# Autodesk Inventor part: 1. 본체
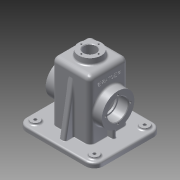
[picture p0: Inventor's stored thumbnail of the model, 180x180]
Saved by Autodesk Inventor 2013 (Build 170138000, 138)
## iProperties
Created: 2016-01
Part Number: 1. 본체
Material: 알루미늄 6061
Document SubType Name: Modeling
Designer: Administrator
Density: 2.71 g/cm^3
Mass: 875.229 g
Surface Area: 901.683 cm^2
Volume: 322.963 cm^3
Author: Administrator
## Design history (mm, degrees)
sketch "스케치1"
  geometry: L1 (65, -57.5)-(-65, -57.5); L2 (-65, -57.5)-(-65, 57.5); L3 (-65, 57.5)-(65, 57.5); L4 (65, 57.5)-(65, -57.5); L5 (65, -57.5)-(-65, 57.5); L6 (-65, -57.5)-(65, 57.5); 1 further point
  constraints: 12 end point, 2 midpoint, 2 parallel, 1 horizontal, 1 perpendicular
  dimensions: "d0" = 130 distance of L2.end L3.end; "d2" = 115 distance of L3.end L1.start
extrude "돌출1" new body sketch "스케치1" distance "d3" = 8; taper "d4" = 0 deg
fillet "모깎기1" dims "d5" = 15
sketch "스케치2"
  geometry: C1 r 7.5 at (-50, -42.5); C2 r 7.5 at (-50, 42.5); C3 r 7.5 at (50, -42.5); C4 r 7.5 at (50, 42.5); A1 r 15 centre (-50, -42.5) between (-65, -42.5) and (-50, -57.5) reference; A2 r 15 centre (50, -42.5) between (50, -57.5) and (65, -42.5) reference; A3 r 15 centre (50, 42.5) between (65, 42.5) and (50, 57.5) reference; A4 r 15 centre (-50, 42.5) between (-50, 57.5) and (-65, 42.5) reference; 1 further point
  constraints: 4 centre point, 4 coincident
  dimensions: "d6" = 15 diameter of C1; "d7" = 15 diameter of C2; "d8" = 15 diameter of C3; "d9" = 15 diameter of C4
extrude "돌출2" join sketch "스케치2" distance "d10" = 3; taper "d11" = 0 deg
sketch "스케치3"
  geometry: L1 (50, 52.5)-(-50, 52.5); L2 (-60, 42.5)-(-60, -42.5); L3 (-50, -52.5)-(50, -52.5); L4 (60, -42.5)-(60, 42.5); L5 (60, 52.5)-(-60, -52.5); L6 (-60, 52.5)-(60, -52.5); A1 r 10 centre (-50, -42.5) between (-60, -42.5) and (-50, -52.5); A2 r 10 centre (50, -42.5) between (50, -52.5) and (60, -42.5); A3 r 10 centre (50, 42.5) between (60, 42.5) and (50, 52.5); A4 r 10 centre (-50, 42.5) between (-50, 52.5) and (-60, 42.5); 1 further point
  constraints: 12 end point, 8 point on circle, 8 point on line, 8 tangent, 4 centre point, 3 equal radius, 2 midpoint, 2 parallel, 1 horizontal, 1 perpendicular
  dimensions: "d12" = 120 distance of L5.start L6.start; "d14" = 105 distance of L6.start L5.end; "d15" = 10 radius of A1
extrude "돌출3" join sketch "스케치3" distance "d16" = 2; taper "d17" = 0 deg
sketch "스케치4"
  geometry: C1 r 7.5 at (0, 0) reference; C2 r 7.5 at (100, -85) reference; C3 r 7.5 at (0, -85) reference; C4 r 7.5 at (0, 0) reference; C5 r 7.5 at (100, 0) reference; C6 r 7.5 at (100, -85) reference; C7 r 7.5 at (0, -85) reference; C8 r 7.5 at (0, 0) reference; C9 r 7.5 at (100, 0) reference; 1 further point
hole "구멍1" sketch "스케치4" at (0, 0), (0, -85), (100, 0), (100, -85) diameter "d18" = 5; stored, may be unused: countersink angle "d22" = 90 deg, drill point angle "d24" = 118 deg; dims "d19" = 6, "d20" = 4, "d21" = 2, "d23" = 8
sketch "스케치5"
  geometry: L1 (-32.5, -32.5)-(32.5, -32.5); L2 (32.5, -32.5)-(32.5, 32.5); L3 (32.5, 32.5)-(-32.5, 32.5); L4 (-32.5, 32.5)-(-32.5, -32.5); L5 (-32.5, -32.5)-(32.5, 32.5); L6 (32.5, -32.5)-(-32.5, 32.5); 1 further point
  constraints: 12 end point, 2 midpoint, 2 parallel, 1 horizontal, 1 perpendicular
  dimensions: "d25" = 65 distance of L2.end L3.end; "d27" = 65 distance of L1.end L2.end
extrude "돌출4" join sketch "스케치5" distance "d28" = 100; taper "d29" = 0 deg
fillet "모깎기2" dims "d30" = 8
fillet "모깎기3" dims "d31" = 8
sketch "스케치6"
  geometry: C1 r 20 at (0, 0); 1 further point
  constraints: 1 centre point, 1 coincident
  dimensions: "d32" = 40 diameter of C1
extrude "돌출5" join sketch "스케치6" distance "d33" = 10; taper "d34" = -5 deg
sketch "스케치7"
  geometry: L1 (27.5, 27.5)-(-27.5, 27.5); L2 (-27.5, 27.5)-(-27.5, -27.5); L3 (-27.5, -27.5)-(27.5, -27.5); L4 (27.5, -27.5)-(27.5, 27.5); L5 (27.5, 27.5)-(-27.5, -27.5); L6 (-27.5, 27.5)-(27.5, -27.5); 1 further point
  constraints: 12 end point, 2 midpoint, 2 parallel, 1 horizontal, 1 perpendicular
  dimensions: "d35" = 55 distance of L2.end L3.end; "d37" = 55 distance of L3.end L1.start
extrude "돌출6" cut sketch "스케치7" distance "d38" = 105; taper "d39" = 0 deg
fillet "모깎기4" dims "d40" = 3
fillet "모깎기5" dims "d41" = 3
sketch "스케치8"
  geometry: C1 r 19.125 at (0, 0) reference
hole "구멍2" sketch "스케치8" at (0, 0) diameter "d42" = 21; stored, may be unused: countersink angle "d46" = 90 deg, drill point angle "d48" = 118 deg; dims "d43" = 6, "d44" = 4, "d45" = 2, "d47" = 8
node "작업 평면2"
sketch "스케치9"
  geometry: L1 (8, -33)-(0, -33) reference; L2 (0, -33)-(0, -25.071) reference; L3 (0, -25.071)-(-3, -25.071) reference; L4 (-3, -25.071)-(-3, -18) reference; L5 (-3, -18)-(10, -18) reference; L6 (10, 67)-(10, -18) reference; L7 (-3, 67)-(10, 67) reference; L8 (-3, 67)-(-3, 74.071) reference; L9 (-3, 74.071)-(0, 74.071) reference; L10 (0, 74.071)-(0, 82) reference; L11 (0, 82)-(8, 82) reference; L12 (8, 82)-(8, 77) reference; L13 (8, 77)-(10, 77) reference; L14 (10, 77)-(10, 67) reference; L15 (8, -28)-(8, -33) reference; L16 (10, -28)-(8, -28) reference; L17 (10, -18)-(10, -28) reference; L18 (-3, -18)-(-3, -10.929) reference; L19 (-3, -10.929)-(0, -10.929) reference; L20 (0, -10.929)-(0, 59.929) reference; L21 (0, 59.929)-(-3, 59.929) reference; L22 (-3, 59.929)-(-3, 67) reference; C1 r 27.5 at (-45, 24.5); 1 further point
  constraints: 1 centre point, 1 horizontal alignment
  dimensions: "d50" = 55 diameter of C1; "d51" = 55 distance from line of L6 C1.centre
extrude "돌출7" join sketch "스케치9" stored distance "d52" = 0; taper "d53" = 0 deg
sketch "스케치10"
  geometry: C1 r 27.5 at (0, 0) reference; 1 further point
hole "구멍3" sketch "스케치10" at (0, 0) diameter "d54" = 30; stored, may be unused: countersink angle "d58" = 90 deg, drill point angle "d60" = 118 deg; dims "d55" = 6, "d56" = 35, "d57" = 17, "d59" = 8
sketch "스케치16"
  geometry: C1 r 15 at (0, 0) reference; 1 further point
hole "구멍6" sketch "스케치16" at (0, 0) diameter "d113" = 30; stored, may be unused: countersink angle "d117" = 90 deg, drill point angle "d119" = 118 deg; dims "d114" = 6, "d115" = 35, "d116" = 17, "d118" = 8
sketch "스케치12"
  geometry: C1 r 10.5 at (0, 0) reference; 1 further point
  constraints: 1 horizontal alignment
  dimensions: "d72" = 14.5 distance of C1.centre point (-14.5, 0)
hole "구멍5" sketch "스케치12" at (-14.5, 0) diameter "d73" = 2.459; stored, may be unused: countersink angle "d77" = 90 deg, drill point angle "d79" = 118 deg; dims "d74" = 7, "d75" = 4, "d76" = 2, "d78" = 9
sketch "스케치13"
  geometry: L1 (19.125, 118)-(20, 108) reference; L2 (20, 108)-(24.5, 108) reference; L3 (32.5, 100)-(32.5, 80.5) reference; L4 (32.5, 80.5)-(47.5, 80.5) reference; L5 (47.5, 80.5)-(47.5, 70.5) reference; L6 (30.5, 68)-(27.5, 68) reference; L7 (27.5, 68)-(27.5, 100) reference; L8 (24.5, 103)-(10.5, 103) reference; L9 (10.5, 103)-(10.5, 118) reference; L10 (10.5, 118)-(13.271, 118) reference; L11 (13.271, 118)-(13.271, 109) reference; L12 (13.271, 109)-(14.5, 108.261) reference; L13 (14.5, 108.261)-(15.73, 109) reference; L14 (15.73, 109)-(15.73, 118) reference; L15 (15.73, 118)-(19.125, 118) reference; L16 (-20, 108)-(-19.125, 118) reference; L17 (-19.125, 118)-(-15.73, 118) reference; L18 (-15.73, 118)-(-15.73, 109) reference; L19 (-15.73, 109)-(-14.5, 108.261) reference; L20 (-14.5, 108.261)-(-13.271, 109) reference; L21 (-13.271, 109)-(-13.271, 118) reference; L22 (-13.271, 118)-(-10.5, 118) reference; L23 (-10.5, 118)-(-10.5, 103) reference; L24 (-10.5, 103)-(-24.5, 103) reference; L25 (-27.5, 100)-(-27.5, 68) reference; L26 (-27.5, 68)-(-30.5, 68) reference; L27 (-47.5, 70.5)-(-47.5, 80.5) reference; L28 (-47.5, 80.5)-(-32.5, 80.5) reference; L29 (-32.5, 80.5)-(-32.5, 100) reference; L30 (-24.5, 108)-(-20, 108) reference; L31 (-60, -2)-(-60, 0) reference; L32 (-60, 0)-(-65, 0) reference; L33 (-65, 0)-(-65, 8) reference; L34 (-65, 8)-(-32.5, 8) reference; L35 (-32.5, 8)-(-32.5, 25.5) reference; L36 (-32.5, 25.5)-(-47.5, 25.5) reference; L37 (-47.5, 25.5)-(-47.5, 35.5) reference; L38 (-30.5, 38)-(-27.5, 38) reference; L39 (-27.5, 38)-(-27.5, -2) reference; L40 (-27.5, -2)-(-60, -2) reference; L41 (60, 0)-(60, -2) reference; L42 (60, -2)-(27.5, -2) reference; L43 (27.5, -2)-(27.5, 38) reference; L44 (27.5, 38)-(30.5, 38) reference; L45 (47.5, 35.5)-(47.5, 25.5) reference; L46 (47.5, 25.5)-(32.5, 25.5) reference; L47 (32.5, 25.5)-(32.5, 8) reference; L48 (32.5, 8)-(65, 8) reference; L49 (65, 8)-(65, 0) reference; L50 (65, 0)-(60, 0) reference; L51 (-42.5, 25.5)-(-42.5, 8); L52 (47.5, 70.5)-(30.5, 70.5) reference; L53 (30.5, 70.5)-(30.5, 68) reference; L54 (-30.5, 68)-(-30.5, 70.5) reference; L55 (-30.5, 70.5)-(-47.5, 70.5) reference; L56 (-47.5, 35.5)-(-30.5, 35.5) reference; L57 (-30.5, 35.5)-(-30.5, 38) reference; L58 (30.5, 38)-(30.5, 35.5) reference; L59 (30.5, 35.5)-(47.5, 35.5) reference; A1 r 8 centre (24.5, 100) between (32.5, 100) and (24.5, 108) reference; A2 r 3 centre (24.5, 100) between (27.5, 100) and (24.5, 103) reference; A3 r 3 centre (-24.5, 100) between (-24.5, 103) and (-27.5, 100) reference; A4 r 8 centre (-24.5, 100) between (-24.5, 108) and (-32.5, 100) reference; 1 further point
  constraints: 2 end point, 2 point on line, 1 vertical
  dimensions: "d83" = 15 distance between parallel lines of L51 L39
feature "리브1" sketch "스케치13" dims "d84" = 1, "d85" = 6, "d86" = 0, "d87" = 0, "d88" = 1, "d89" = 1
sketch "스케치14"
  geometry: L1 (13.271, 109)-(14.5, 108.261) reference; L2 (14.5, 108.261)-(15.73, 109) reference; L3 (15.73, 109)-(15.73, 118) reference; L4 (15.73, 118)-(19.125, 118) reference; L5 (19.125, 118)-(20, 108) reference; L6 (20, 108)-(24.5, 108) reference; L7 (32.5, 100)-(32.5, 8) reference; L8 (32.5, 8)-(57.5, 8) reference; L9 (57.5, 8)-(57.5, 0) reference; L10 (57.5, 0)-(52.5, 0) reference; L11 (52.5, 0)-(52.5, -2) reference; L12 (52.5, -2)-(27.5, -2) reference; L13 (27.5, -2)-(27.5, 100) reference; L14 (24.5, 103)-(10.5, 103) reference; L15 (10.5, 103)-(10.5, 118) reference; L16 (10.5, 118)-(13.271, 118) reference; L17 (13.271, 118)-(13.271, 109) reference; L18 (-14.5, 108.261)-(-13.271, 109) reference; L19 (-13.271, 109)-(-13.271, 118) reference; L20 (-13.271, 118)-(-10.5, 118) reference; L21 (-10.5, 118)-(-10.5, 103) reference; L22 (-10.5, 103)-(-24.5, 103) reference; L23 (-27.5, 100)-(-27.5, -2) reference; L24 (-27.5, -2)-(-52.5, -2) reference; L25 (-52.5, -2)-(-52.5, 0) reference; L26 (-52.5, 0)-(-57.5, 0) reference; L27 (-57.5, 0)-(-57.5, 8) reference; L28 (-57.5, 8)-(-32.5, 8) reference; L29 (-32.5, 8)-(-32.5, 100) reference; L30 (-24.5, 108)-(-20, 108) reference; L31 (-20, 108)-(-19.125, 118) reference; L32 (-19.125, 118)-(-15.73, 118) reference; L33 (-15.73, 118)-(-15.73, 109) reference; L34 (-15.73, 109)-(-14.5, 108.261) reference; L35 (32.5, 93.069)-(47.5, 8); A1 r 8 centre (24.5, 100) between (32.5, 100) and (24.5, 108) reference; A2 r 3 centre (24.5, 100) between (27.5, 100) and (24.5, 103) reference; A3 r 3 centre (-24.5, 100) between (-24.5, 103) and (-27.5, 100) reference; A4 r 8 centre (-24.5, 100) between (-24.5, 108) and (-32.5, 100) reference; 1 further point
  constraints: 2 end point, 2 point on line
  dimensions: "d90" = 10 deg angle of L9 L35; "d91" = 10 distance from line of L9 L35.end
feature "리브2" sketch "스케치14" dims "d92" = 1, "d93" = 10, "d94" = 0, "d95" = 0, "d96" = 1, "d97" = 1
sketch "스케치15"
  geometry: L1 (0, 0)-(0, 49) reference; L2 (34.51, 49)-(0, 49) reference; L3 (74.336, 27.5)-(92, 27.5) reference; L4 (92, 27.5)-(92, 49) reference; L5 (92, 49)-(59.49, 49) reference; L6 (34.51, 0)-(0, 0) reference; L7 (92, 0)-(59.49, 0) reference; L8 (92, -33)-(92, 0) reference; L9 (100, -33)-(92, -33) reference; L10 (100, -28)-(100, -33) reference; L11 (102, -28)-(100, -28) reference; L12 (102, 77)-(102, -28) reference; L13 (100, 77)-(102, 77) reference; L14 (100, 82)-(100, 77) reference; L15 (92, 82)-(100, 82) reference; L16 (92, 49)-(92, 82) reference; L17 (92, 21.5)-(74.336, 21.5) reference; L18 (92, 0)-(92, 21.5) reference; L19 (-18, 5.375)-(-18, 43.625) reference; L20 (0, -8)-(92, -8) reference; C1 r 17.5 at (47, 24.5) reference; A1 r 27.5 centre (47, 24.5) between (59.49, 49) and (34.51, 49) reference; A2 r 27.5 centre (47, 24.5) between (74.336, 27.5) and (59.49, 49) reference; A3 r 27.5 centre (47, 24.5) between (34.51, 0) and (59.49, 0) reference; A4 r 27.5 centre (47, 24.5) between (34.51, 49) and (34.51, 0) reference; A5 r 27.5 centre (47, 24.5) between (59.49, 0) and (74.336, 21.5) reference; 2 further points
  constraints: 1 other
  dimensions: "d98" = 27 distance from line of point (9, 24.5) L19; "d99" = 32.5 distance from line of L20 point (9, 24.5)
feature "엠보싱1" sketch "스케치15" dims "d100" = 0.5, "d101" = 0
fillet "모깎기6" dims "d102" = 3
fillet "모깎기7" dims "d103" = 3
fillet "모깎기8" dims "d104" = 3
fillet "모깎기9" dims "d105" = 3
fillet "모깎기10" dims "d106" = 1
fillet "모깎기11" dims "d107" = 3
fillet "모깎기12" dims "d108" = 3
fillet "모깎기13" dims "d109" = 3
fillet "모깎기14" dims "d110" = 3
fillet "모깎기15" dims "d111" = 3
fillet "모깎기16" dims "d112" = 3
sketch "스케치17"
  geometry: C1 r 17.5 at (0, 0) reference; 2 further points
  constraints: 1 vertical alignment
  dimensions: "d120" = 21 distance of C1.centre point (0, -21)
hole "구멍7" sketch "스케치17" at (0, -21) diameter "d121" = 3.242; stored, may be unused: countersink angle "d125" = 90 deg, drill point angle "d127" = 118 deg; dims "d122" = 8, "d123" = 35, "d124" = 17, "d126" = 10
fillet "모깎기17" dims "d131" = 0.3
fillet "모깎기18" dims "d132" = 0.3
chamfer "모따기1" distance "d133" = 1; stored, may be unused: second distance "d134" = 2, angle "d135" = 45 deg
fillet "모깎기19" dims "d136" = 3
node "솔리드1"
mirror "대칭1"
pattern_circular "원형 패턴2" dims angle "d81" = 360 deg
mirror "대칭3"
mirror "대칭4"
pattern_circular "원형 패턴3" dims angle "d129" = 360 deg
mirror "대칭5"
node "절단 모서리 투영1"
node "절단 모서리 투영2"
node "절단 모서리 투영3"
node "절단 모서리 투영4"
node "절단 모서리 투영5"
node "절단 모서리 투영6"
other parameters: "d49" = 15
